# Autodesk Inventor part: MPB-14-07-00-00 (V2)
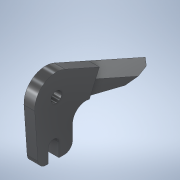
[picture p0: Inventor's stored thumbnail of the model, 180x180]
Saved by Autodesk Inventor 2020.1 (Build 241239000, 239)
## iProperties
Created: 2020-04
Part Number: MPB-14-07-00-00 (V2)
Material: CK55
Document SubType Name: Modeling
Designer: Safarabadi
Density: 7.85 g/cm^3
Appearance: CK55
Author: Safarabadi
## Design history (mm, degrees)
derived "MPB-14-07-00-00.ipt"
  workplane "Work Plane1"
feature "Solid1::MPB-14-07-00-00.ipt" dims "d0" = 10
tag "TaggingFeature1"
body "Solid1"
